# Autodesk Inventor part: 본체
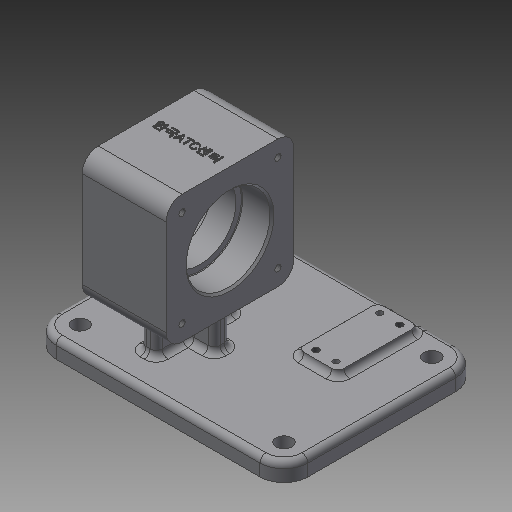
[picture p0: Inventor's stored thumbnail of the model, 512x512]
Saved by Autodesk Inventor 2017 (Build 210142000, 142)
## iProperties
Created: 2019-09
Part Number: 본체
Material: 일반
Document SubType Name: Modeling
Designer: mduedu
Density: 1 g/cm^3
Appearance: 기본값
Author: mduedu
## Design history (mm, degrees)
sketch "스케치1"
  geometry: L1 (42, -62)-(-84, -62); L2 (-84, -62)-(-84, 36); L3 (-84, 36)-(42, 36); L4 (42, 36)-(42, -62); 1 further point
  constraints: 8 end point, 2 parallel, 1 horizontal, 1 perpendicular
  dimensions: "d0" = 36 distance from line of L3 point (0, 0); "d1" = 98 distance of L1.end L2.end; "d2" = 42 distance from line of L4 point (0, 0); "d3" = 126 distance of L2.end L3.end
extrude "돌출1" new body sketch "스케치1" distance "d4" = 9; taper "d5" = 0 deg
sketch "스케치2"
  geometry: L1 (0, -62)-(0, 36) reference; L2 (27, -32)-(91, -32); L3 (91, -32)-(91, 32); L4 (91, 32)-(27, 32); L5 (27, 32)-(27, -32); L6 (27, -32)-(91, 32); L7 (91, -32)-(27, 32); 3 further points
  constraints: 12 end point, 3 midpoint, 2 parallel, 1 horizontal, 1 horizontal alignment, 1 perpendicular
  dimensions: "d87" = 64 distance of L4.end L3.end; "d88" = 64 distance of L3.end L2.end; "d89" = 59 distance from line of point (59, 0) L1
extrude "돌출2" join sketch "스케치2" stored distance "d8" = 42; taper "d9" = 0 deg
sketch "스케치3"
  geometry: L1 (-17, 4)-(17, 4); L2 (17, 4)-(17, -4); L3 (17, -4)-(-17, -4); L4 (-17, -4)-(-17, 4); L5 (-4, 20)-(4, 20); L6 (4, 20)-(4, -20); L7 (4, -20)-(-4, -20); L8 (-4, -20)-(-4, 20); 5 further points
  constraints: 16 end point, 4 midpoint, 4 parallel, 2 horizontal, 2 horizontal alignment, 2 perpendicular, 2 vertical alignment
  dimensions: "d10" = 8 distance of L5.start L5.end; "d12" = 8 distance of L1.end L2.end; "d13" = 34 distance of L2.end L3.end; "d14" = 40 distance of L5.end L6.end
extrude "돌출3" join sketch "스케치3" stored distance "d15" = 42; taper "d16" = 0 deg
sketch "스케치4"
  geometry: L1 (-32, 91)-(-32, 27) reference; L2 (32, 91)-(-32, 91) reference; L3 (32, 27)-(32, 91) reference; L4 (-32, 27)-(32, 27) reference; C1 r 21 at (0, 59); 3 further points
  constraints: 2 midpoint, 1 centre point, 1 horizontal alignment, 1 vertical alignment
  dimensions: "d17" = 42 diameter of C1
extrude "돌출4" cut sketch "스케치4" distance "d18" = 15; taper "d19" = 0 deg
hole "구멍1" diameter "d22" = 36; stored, may be unused: countersink angle "d26" = 90 deg, drill point angle "d28" = 118 deg; dims "d20" = 10, "d21" = 10, "d23" = 6, "d24" = 4, "d25" = 2, "d27" = 8
fillet "모깎기1" dims "d29" = 0.3
chamfer "모따기1" distance "d30" = 1; stored, may be unused: second distance "d31" = 2, angle "d32" = 45 deg
fillet "모깎기9" dims "d90" = 8
sketch "스케치11"
  geometry: L1 (-24, 27)-(24, 27) reference; L2 (32, 35)-(32, 83) reference; L3 (24, 91)-(-24, 91) reference; L4 (-32, 83)-(-32, 35) reference; C1 r 22 at (0, 59) reference; A1 r 8 centre (-24, 35) between (-32, 35) and (-24, 27) reference; A2 r 8 centre (24, 35) between (24, 27) and (32, 35) reference; A3 r 8 centre (24, 83) between (32, 83) and (24, 91) reference; A4 r 8 centre (-24, 83) between (-24, 91) and (-32, 83) reference; 5 further points
  constraints: 4 coincident
hole "구멍6" sketch "스케치11" at (-24, 83), (24, 83), (24, 35), (-24, 35) diameter "d91" = 3.242; stored, may be unused: countersink angle "d95" = 90 deg, drill point angle "d97" = 118 deg; dims "d92" = 8, "d93" = 4, "d94" = 2, "d96" = 10
fillet "모깎기2" dims "d44" = 12
sketch "스케치6"
  geometry: L1 (-42, 50)-(-42, -24) reference; L2 (-30, -36)-(72, -36) reference; L3 (84, -24)-(84, 50) reference; L4 (72, 62)-(-30, 62) reference; L5 (17, 4)-(17, -4) reference; L6 (17, -4)-(4, -4) reference; L7 (4, -4)-(4, -20) reference; L8 (4, -20)-(-4, -20) reference; L9 (-4, -20)-(-4, -4) reference; L10 (-4, -4)-(-17, -4) reference; L11 (-17, -4)-(-17, 4) reference; L12 (-17, 4)-(-4, 4) reference; L13 (-4, 4)-(-4, 20) reference; L14 (-4, 20)-(4, 20) reference; L15 (4, 20)-(4, 4) reference; L16 (4, 4)-(17, 4) reference; A1 r 12 centre (-30, 50) between (-30, 62) and (-42, 50) reference; A2 r 12 centre (-30, -24) between (-42, -24) and (-30, -36) reference; A3 r 12 centre (72, -24) between (72, -36) and (84, -24) reference; A4 r 12 centre (72, 50) between (84, 50) and (72, 62) reference; 5 further points
  constraints: 4 coincident
hole "구멍3" sketch "스케치6" at (-30, 50), (72, 50), (72, -24), (-30, -24) diameter "d45" = 8; stored, may be unused: countersink angle "d49" = 90 deg, drill point angle "d51" = 118 deg; dims "d46" = 8, "d47" = 4, "d48" = 2, "d50" = 10
sketch "스케치7"
  geometry: L1 (38, 57)-(58, 57); L2 (58, 57)-(58, 17); L3 (58, 17)-(38, 17); L4 (38, 17)-(38, 57); L5 (72, 62)-(-30, 62) reference; 3 further points
  constraints: 8 end point, 2 midpoint, 2 parallel, 1 horizontal, 1 perpendicular
  dimensions: "d52" = 48 horizontal distance of point (48, 57) point (0, 0); "d53" = 20 distance of L1.start L1.end; "d54" = 40 distance of L1.end L2.end; "d55" = 25 distance from line of point (38, 37) L5
extrude "돌출5" join sketch "스케치7" distance "d56" = 3; taper "d57" = 0 deg
fillet "모깎기3" dims "d58" = 3
fillet "모깎기4" dims "d59" = 3
fillet "모깎기5" dims "d60" = 3
fillet "모깎기6" dims "d61" = 3
fillet "모깎기7" dims "d62" = 3
fillet "모깎기8" dims "d63" = 3
sketch "스케치8"
  geometry: L1 (72, 62)-(58.317, 62) reference; L2 (84, -24)-(84, 50) reference; C1 r 1.5 at (43, 53); C2 r 1.5 at (53, 21); 1 further point
  constraints: 2 centre point, 1 equal radius
  dimensions: "d64" = 3 diameter of C1; "d65" = 9 distance from line of C1.centre L1; "d66" = 32 vertical distance of C2.centre C1.centre; "d67" = 10 horizontal distance of C2.centre C1.centre; "d68" = 31 distance from line of L2 C2.centre
hole "구멍4" sketch "스케치8" at (43, 53), (53, 21) diameter "d69" = 3; stored, may be unused: countersink angle "d73" = 90 deg, drill point angle "d75" = 118 deg; dims "d70" = 8, "d71" = 4, "d72" = 2, "d74" = 6
sketch "스케치9"
  geometry: C1 r 1.5 at (43, 53) reference; C2 r 1.5 at (53, 21) reference; 3 further points
  constraints: 2 horizontal alignment, 2 vertical alignment
hole "구멍5" sketch "스케치9" at (53, 53), (43, 21) diameter "d76" = 3.242; stored, may be unused: countersink angle "d80" = 90 deg, drill point angle "d82" = 118 deg; dims "d77" = 6, "d78" = 4, "d79" = 2, "d81" = 8
sketch "스케치10"
  geometry: 2 further points
  constraints: 1 coincident, 1 other
feature "엠보싱1" sketch "스케치10" dims "d0" = 36, "d1" = 98, "d2" = 42, "d3" = 126, "d12" = 8, "d13" = 34, "d85" = 0.5, "d86" = 0
node "솔리드1"
mirror "대칭1"
mirror "대칭2"
node "투영된 루프1"
node "투영된 루프2"
